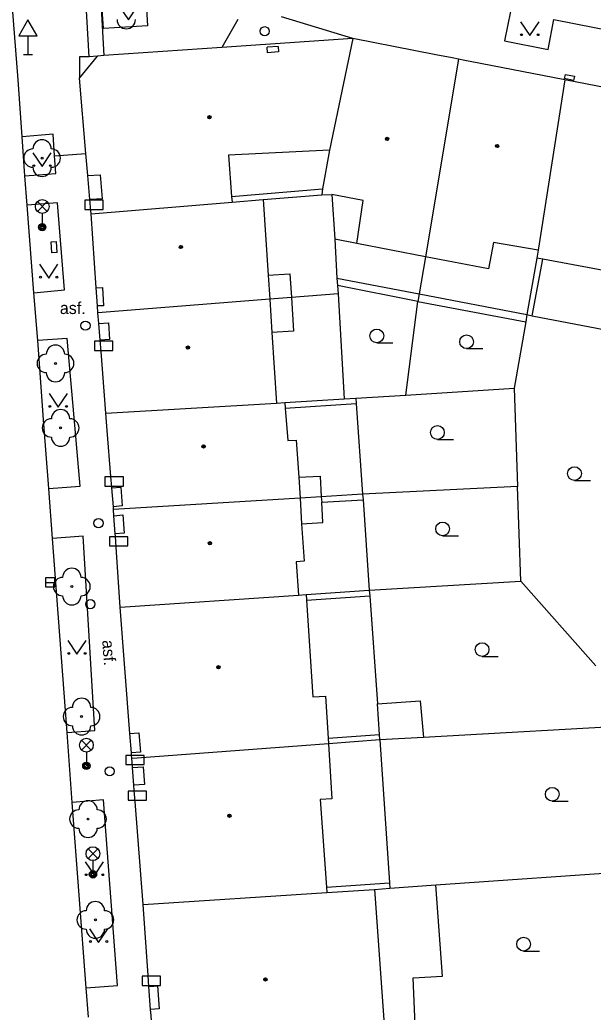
# Model space of a CAD drawing. Extents: x -596229 to -595156, y -1161237 to -1159376.
# Drawn here: x -596087.1 to -596055.9, y -1160946.5 to -1160892.5 of the extents above; entities that cross this region are included whole.
import ezdxf

# ---------------------------------------------------------------- set-up
doc = ezdxf.new("R2010")
doc.units = 0
for name, color, linetype in [('DOP - kresba z DSPS bez souradnic', 7, 'Continuous'), ('DOP - rozhrani ploch obecne', 7, 'Continuous'), ('Level 22', 7, 'Continuous'), ('Level 24', 7, 'Continuous'), ('Level 26', 7, 'Continuous'), ('Level 27', 7, 'Continuous'), ('Level 28', 7, 'Continuous'), ('Level 33', 7, 'Continuous'), ('Level 34', 7, 'Continuous'), ('Level 36', 7, 'Continuous'), ('Level 39', 7, 'Continuous'), ('plynovod - povrch.  znaky - PRIS skut. velikost', 7, 'Continuous'), ('slaboproud - povrch.  znaky a tel. budka skut. velikost', 7, 'Continuous'), ('Specificka linie pasportu komunikaci', 7, 'Continuous'), ('TM - budovy zdene_ betonove - NP', 7, 'Continuous'), ('TM - budovy zdene_ betonove - VN', 7, 'Continuous'), ('TM - budovy zdene_ betonove - VP', 7, 'Continuous'), ('TM - chodniky - VP', 7, 'Continuous'), ('TM - komunikace - VP', 7, 'Continuous'), ('TM - letecke snimky - pomocna linie', 7, 'Continuous'), ('TM - popis povrchu', 7, 'Continuous'), ('TM - rozhrani mezi zpev. plochami mezi sebou - VP', 7, 'Continuous'), ('TM - vstup do budovy - zdene_ betonove', 7, 'Continuous')]:
    doc.layers.add(name, color=color, linetype=linetype)

msp = doc.modelspace()

# ---------------------------------------------------------------- linework, layer by layer
at = {"layer": 'DOP - kresba z DSPS bez souradnic'}
for points in [[(-596075.59, -1160902.13), (-596070.64, -1160901.72)], [(-596068.78, -1160904.69), (-596069.98, -1160904.45)], [(-596059.23, -1160908.62), (-596058.65, -1160905.54)], [(-596073.61, -1160906.41), (-596072.42, -1160906.34)], [(-596072.42, -1160906.34), (-596072.34, -1160907.63)], [(-596069.86, -1160906.57), (-596065.38, -1160907.43)], [(-596072.34, -1160907.63), (-596072.22, -1160909.46)], [(-596065.38, -1160907.43), (-596059.52, -1160908.56)], [(-596072.22, -1160909.46), (-596073.4, -1160909.54)], [(-596072.67, -1160913.65), (-596068.81, -1160913.41)], [(-596071.94, -1160917.42), (-596070.78, -1160917.35)], [(-596070.78, -1160917.35), (-596070.71, -1160918.48)], [(-596070.71, -1160918.48), (-596070.69, -1160918.78)], [(-596070.69, -1160918.78), (-596068.44, -1160918.64)], [(-596070.62, -1160919.88), (-596070.69, -1160918.78)], [(-596071.78, -1160919.95), (-596070.62, -1160919.88)], [(-596071.51, -1160924.11), (-596068.07, -1160923.87)], [(-596067.54, -1160931.43), (-596067.66, -1160929.76)], [(-596070.34, -1160931.63), (-596067.54, -1160931.43)], [(-596067.52, -1160931.72), (-596067.54, -1160931.43)], [(-596070.43, -1160939.73), (-596067, -1160939.5)]]:
    msp.add_lwpolyline(points, dxfattribs=at)
at = {"layer": 'DOP - rozhrani ploch obecne'}
for points in [[(-596073.88, -1160902.29), (-596070.69, -1160902.03)], [(-596070.13, -1160902.02), (-596069.98, -1160904.45)], [(-596069.98, -1160904.45), (-596069.86, -1160906.57)], [(-596065.03, -1160905.41), (-596065.38, -1160907.43)], [(-596058.98, -1160905.48), (-596059.52, -1160908.56)], [(-596069.86, -1160906.57), (-596069.83, -1160906.98)], [(-596069.83, -1160906.98), (-596069.8, -1160907.43)], [(-596065.45, -1160907.85), (-596069.83, -1160906.98)], [(-596072.34, -1160907.63), (-596073.52, -1160907.72)], [(-596069.8, -1160907.43), (-596072.34, -1160907.63)], [(-596069.8, -1160907.43), (-596069.46, -1160913.15)], [(-596066.1, -1160912.94), (-596065.45, -1160907.85)], [(-596065.38, -1160907.43), (-596065.45, -1160907.85)], [(-596065.45, -1160907.85), (-596059.58, -1160908.95)], [(-596059.58, -1160908.95), (-596060.21, -1160912.57)], [(-596059.52, -1160908.56), (-596059.58, -1160908.95)], [(-596059.52, -1160908.56), (-596059.23, -1160908.62)], [(-596059.23, -1160908.62), (-596052.19, -1160909.97)], [(-596066.1, -1160912.94), (-596060.21, -1160912.57)], [(-596060.21, -1160912.57), (-596060.03, -1160917.92)], [(-596072.69, -1160913.35), (-596069.46, -1160913.15)], [(-596069.46, -1160913.15), (-596068.83, -1160913.11)], [(-596068.83, -1160913.11), (-596066.1, -1160912.94)], [(-596068.83, -1160913.11), (-596068.81, -1160913.41)], [(-596068.81, -1160913.41), (-596068.46, -1160918.34)], [(-596060.03, -1160917.92), (-596068.46, -1160918.34)], [(-596059.85, -1160923.07), (-596060.03, -1160917.92)], [(-596070.71, -1160918.48), (-596071.87, -1160918.55)], [(-596068.46, -1160918.34), (-596070.71, -1160918.48)], [(-596068.46, -1160918.34), (-596068.44, -1160918.64)], [(-596068.44, -1160918.64), (-596068.1, -1160923.57)], [(-596071.53, -1160923.81), (-596068.1, -1160923.57)], [(-596068.1, -1160923.57), (-596059.85, -1160923.07)], [(-596068.1, -1160923.57), (-596068.07, -1160923.87)], [(-596055.77, -1160927.69), (-596059.85, -1160923.07)], [(-596068.07, -1160923.87), (-596067.66, -1160929.76)], [(-596067.66, -1160929.76), (-596065.32, -1160929.6)], [(-596065.32, -1160929.6), (-596065.15, -1160931.59)], [(-596052.93, -1160930.9), (-596065.15, -1160931.59)], [(-596065.15, -1160931.59), (-596067.52, -1160931.72)], [(-596067.52, -1160931.72), (-596070.32, -1160931.93)], [(-596067.52, -1160931.72), (-596067, -1160939.5)], [(-596064.48, -1160939.62), (-596053.5, -1160938.85)], [(-596067.81, -1160939.86), (-596066.98, -1160939.8)], [(-596067, -1160939.5), (-596066.98, -1160939.8)], [(-596066.98, -1160939.8), (-596064.48, -1160939.62)]]:
    msp.add_lwpolyline(points, dxfattribs=at)
at = {"layer": 'Level 22'}
for centre in [(-596085.91, -1160900.04), (-596085.18, -1160911.22), (-596084.9, -1160914.73), (-596084.29, -1160923.37), (-596083.76, -1160930.45), (-596083.41, -1160936.03), (-596083.01, -1160941.52)]:
    msp.add_circle(centre, 0.05, dxfattribs=at)
for centre, start, end in [((-596081.33, -1160892.5), 180, 0), ((-596085.91, -1160899.54), 0, 180), ((-596086.41, -1160900.04), 90, 270), ((-596085.41, -1160900.04), 270, 90), ((-596085.91, -1160900.54), 180, 0), ((-596085.18, -1160910.72), 0, 180), ((-596085.68, -1160911.22), 90, 270), ((-596084.68, -1160911.22), 270, 90), ((-596085.18, -1160911.72), 180, 0), ((-596084.9, -1160914.23), 0, 180), ((-596085.4, -1160914.73), 90, 270), ((-596084.4, -1160914.73), 270, 90), ((-596084.9, -1160915.23), 180, 0), ((-596084.29, -1160922.87), 0, 180), ((-596084.79, -1160923.37), 90, 270), ((-596083.79, -1160923.37), 270, 90), ((-596084.29, -1160923.87), 180, 0), ((-596083.76, -1160929.95), 0, 180), ((-596084.26, -1160930.45), 90, 270), ((-596083.26, -1160930.45), 270, 90), ((-596083.76, -1160930.95), 180, 0), ((-596083.41, -1160935.53), 0, 180), ((-596083.91, -1160936.03), 90, 270), ((-596082.91, -1160936.03), 270, 90), ((-596083.41, -1160936.53), 180, 0), ((-596083.01, -1160941.02), 0, 180), ((-596083.51, -1160941.52), 90, 270), ((-596082.51, -1160941.52), 270, 90), ((-596083.01, -1160942.02), 180, 0)]:
    msp.add_arc(centre, 0.5, start, end, dxfattribs=at)
at = {"layer": 'Level 24'}
for points in [[(-596083.587, -1160902.838), (-596082.587, -1160902.838), (-596082.587, -1160902.338), (-596083.587, -1160902.338)], [(-596083.057, -1160910.508), (-596082.057, -1160910.508), (-596082.057, -1160910.008), (-596083.057, -1160910.008)], [(-596082.487, -1160917.898), (-596081.487, -1160917.898), (-596081.487, -1160917.398), (-596082.487, -1160917.398)], [(-596082.237, -1160921.158), (-596081.237, -1160921.158), (-596081.237, -1160920.658), (-596082.237, -1160920.658)], [(-596081.357, -1160933.068), (-596080.357, -1160933.068), (-596080.357, -1160932.568), (-596081.357, -1160932.568)], [(-596081.218, -1160935.009), (-596080.218, -1160935.009), (-596080.218, -1160934.509), (-596081.218, -1160934.509)], [(-596080.467, -1160945.088), (-596079.467, -1160945.088), (-596079.467, -1160944.588), (-596080.467, -1160944.588)]]:
    msp.add_lwpolyline(points, close=True, dxfattribs=at)
at = {"layer": 'Level 26'}
msp.add_circle((-596083.28, -1160924.33), 0.25, dxfattribs=at)
at = {"layer": 'Level 27'}
msp.add_line((-596085.72, -1160923.14), (-596085.22, -1160923.14), dxfattribs=at)
msp.add_lwpolyline([(-596085.72, -1160923.39), (-596085.22, -1160923.39), (-596085.22, -1160922.89), (-596085.72, -1160922.89)], close=True, dxfattribs=at)
at = {"layer": 'Level 28'}
for centre in [(-596073.79, -1160893.13), (-596083.55, -1160909.16), (-596082.84, -1160919.92), (-596082.23, -1160933.43)]:
    msp.add_circle(centre, 0.25, dxfattribs=at)
at = {"layer": 'Level 33'}
for p, q in [((-596086.165, -1160902.94), (-596085.635, -1160902.41)), ((-596086.165, -1160902.41), (-596085.635, -1160902.94)), ((-596085.9, -1160903.05), (-596085.9, -1160903.8)), ((-596083.765, -1160932.27), (-596083.235, -1160931.74)), ((-596083.765, -1160931.74), (-596083.235, -1160932.27)), ((-596083.5, -1160932.38), (-596083.5, -1160933.13)), ((-596083.405, -1160938.18), (-596082.875, -1160937.65)), ((-596083.405, -1160937.65), (-596082.875, -1160938.18)), ((-596083.14, -1160938.29), (-596083.14, -1160939.04))]:
    msp.add_line(p, q, dxfattribs=at)
for centre, radius in [((-596085.9, -1160902.675), 0.375), ((-596085.9, -1160903.8), 0.2), ((-596085.9, -1160903.8), 0.145), ((-596085.9, -1160903.8), 0.0876), ((-596083.5, -1160932.005), 0.375), ((-596083.5, -1160933.13), 0.2), ((-596083.5, -1160933.13), 0.145), ((-596083.5, -1160933.13), 0.0876), ((-596083.14, -1160937.915), 0.375), ((-596083.14, -1160939.04), 0.2), ((-596083.14, -1160939.04), 0.145), ((-596083.14, -1160939.04), 0.0876)]:
    msp.add_circle(centre, radius, dxfattribs=at)
at = {"layer": 'Level 34'}
for p, q in [((-596086.68, -1160893.382), (-596086.68, -1160894.4)), ((-596086.93, -1160894.4), (-596086.43, -1160894.4))]:
    msp.add_line(p, q, dxfattribs=at)
msp.add_lwpolyline([(-596087.18, -1160893.382), (-596086.18, -1160893.382), (-596086.68, -1160892.516)], close=True, dxfattribs=at)
at = {"layer": 'Level 36'}
for p, q in [((-596067.69, -1160910.095), (-596066.815, -1160910.095)), ((-596062.8, -1160910.415), (-596061.925, -1160910.415)), ((-596064.39, -1160915.355), (-596063.515, -1160915.355)), ((-596056.93, -1160917.595), (-596056.055, -1160917.595)), ((-596064.11, -1160920.605), (-596063.235, -1160920.605)), ((-596061.96, -1160927.175), (-596061.085, -1160927.175)), ((-596058.14, -1160935.055), (-596057.265, -1160935.055)), ((-596059.7, -1160943.215), (-596058.825, -1160943.215))]:
    msp.add_line(p, q, dxfattribs=at)
for points in [[(-596081.71, -1160891.76), (-596081.21, -1160892.51), (-596080.71, -1160891.76)], [(-596059.86, -1160892.62), (-596059.36, -1160893.37), (-596058.86, -1160892.62)], [(-596086.41, -1160899.75), (-596085.91, -1160900.5), (-596085.41, -1160899.75)], [(-596086.05, -1160905.82), (-596085.55, -1160906.57), (-596085.05, -1160905.82)], [(-596085.53, -1160912.86), (-596085.03, -1160913.61), (-596084.53, -1160912.86)], [(-596084.51, -1160926.31), (-596084.01, -1160927.06), (-596083.51, -1160926.31)], [(-596083.56, -1160938.36), (-596083.06, -1160939.11), (-596082.56, -1160938.36)], [(-596083.33, -1160942), (-596082.83, -1160942.75), (-596082.33, -1160942)]]:
    msp.add_lwpolyline(points, dxfattribs=at)
for centre, radius in [((-596059.81, -1160893.32), 0.05), ((-596058.911, -1160893.32), 0.05), ((-596086.36, -1160900.45), 0.05), ((-596085.461, -1160900.45), 0.05), ((-596086, -1160906.52), 0.05), ((-596085.101, -1160906.52), 0.05), ((-596067.69, -1160909.72), 0.375), ((-596062.8, -1160910.04), 0.375), ((-596085.48, -1160913.56), 0.05), ((-596084.581, -1160913.56), 0.05), ((-596064.39, -1160914.98), 0.375), ((-596056.93, -1160917.22), 0.375), ((-596064.11, -1160920.23), 0.375), ((-596061.96, -1160926.8), 0.375), ((-596084.46, -1160927.01), 0.05), ((-596083.561, -1160927.01), 0.05), ((-596058.14, -1160934.68), 0.375), ((-596083.51, -1160939.06), 0.05), ((-596082.611, -1160939.06), 0.05), ((-596059.7, -1160942.84), 0.375), ((-596083.28, -1160942.7), 0.05), ((-596082.381, -1160942.7), 0.05)]:
    msp.add_circle(centre, radius, dxfattribs=at)
at = {"layer": 'Level 39'}
for centre, radius in [((-596076.8, -1160897.81), 0.09), ((-596076.8, -1160897.81), 0.0398), ((-596067.13, -1160898.99), 0.09), ((-596067.13, -1160898.99), 0.0398), ((-596061.14, -1160899.38), 0.09), ((-596061.14, -1160899.38), 0.0398), ((-596078.35, -1160904.88), 0.09), ((-596078.35, -1160904.88), 0.0398), ((-596077.97, -1160910.36), 0.09), ((-596077.97, -1160910.36), 0.0398), ((-596077.12, -1160915.74), 0.09), ((-596077.12, -1160915.74), 0.0398), ((-596076.77, -1160921.01), 0.09), ((-596076.77, -1160921.01), 0.0398), ((-596076.31, -1160927.76), 0.09), ((-596076.31, -1160927.76), 0.0398), ((-596075.71, -1160935.85), 0.09), ((-596075.71, -1160935.85), 0.0398), ((-596073.75, -1160944.76), 0.09), ((-596073.75, -1160944.76), 0.0398)]:
    msp.add_circle(centre, radius, dxfattribs=at)
at = {"layer": 'plynovod - povrch.  znaky - PRIS skut. velikost'}
for points in [[(-596073.06, -1160893.96), (-596073.66, -1160894)], [(-596073.06, -1160893.96), (-596073.04, -1160894.26), (-596073.64, -1160894.3), (-596073.66, -1160894)]]:
    msp.add_lwpolyline(points, dxfattribs=at)
at = {"layer": 'slaboproud - povrch.  znaky a tel. budka skut. velikost'}
for points in [[(-596057.41, -1160895.48), (-596056.93, -1160895.58), (-596056.98, -1160895.82), (-596057.47, -1160895.71), (-596057.41, -1160895.48)], [(-596085.08, -1160905.18), (-596085.38, -1160905.2), (-596085.42, -1160904.6), (-596085.12, -1160904.58)], [(-596085.08, -1160905.18), (-596085.12, -1160904.58)]]:
    msp.add_lwpolyline(points, dxfattribs=at)
at = {"layer": 'Specificka linie pasportu komunikaci'}
for points in [[(-596075.26, -1160892.49), (-596076.12, -1160894.01)], [(-596069, -1160893.53), (-596072.87, -1160892.34)]]:
    msp.add_lwpolyline(points, dxfattribs=at)
at = {"layer": 'TM - budovy zdene_ betonove - NP'}
for points in [[(-596083.42, -1160900.99), (-596082.75, -1160900.95), (-596082.64, -1160902.26), (-596082.94, -1160902.27), (-596083.31, -1160902.29)], [(-596082.96, -1160907.1), (-596082.63, -1160907.08), (-596082.57, -1160908.08), (-596082.89, -1160908.09)], [(-596082.82, -1160909.04), (-596082.3, -1160909), (-596082.24, -1160909.91), (-596082.75, -1160909.95)], [(-596082.12, -1160918), (-596081.63, -1160917.96), (-596081.55, -1160918.98)], [(-596081.55, -1160918.98), (-596082.03, -1160919.02)], [(-596082, -1160919.51), (-596081.51, -1160919.47), (-596081.44, -1160920.46), (-596081.93, -1160920.5)], [(-596081.13, -1160931.37), (-596080.64, -1160931.33), (-596080.56, -1160932.38), (-596081.05, -1160932.42)], [(-596080.98, -1160933.22), (-596080.4, -1160933.18), (-596080.33, -1160934.15), (-596080.91, -1160934.19)], [(-596080.09, -1160945.15), (-596079.83, -1160945.13), (-596079.63, -1160945.11), (-596079.53, -1160946.36), (-596080, -1160946.4)]]:
    msp.add_lwpolyline(points, dxfattribs=at)
at = {"layer": 'TM - budovy zdene_ betonove - VN'}
for points in [[(-596083.35, -1160894.53), (-596083.87, -1160894.53), (-596083.88, -1160895.68)], [(-596082.89, -1160894.49), (-596083.35, -1160894.53)]]:
    msp.add_lwpolyline(points, dxfattribs=at)
at = {"layer": 'TM - budovy zdene_ betonove - VP'}
for points in [[(-596069, -1160893.53), (-596076.12, -1160894.01)], [(-596069, -1160893.53), (-596070.26, -1160899.6)], [(-596064.47, -1160894.41), (-596069, -1160893.53)], [(-596076.12, -1160894.01), (-596082.55, -1160894.45)], [(-596083.88, -1160895.68), (-596082.89, -1160894.49)], [(-596082.55, -1160894.45), (-596082.89, -1160894.49)], [(-596063.24, -1160894.65), (-596065.03, -1160905.41)], [(-596063.24, -1160894.65), (-596063.58, -1160894.58)], [(-596062.89, -1160894.72), (-596063.24, -1160894.65)], [(-596057.46, -1160895.78), (-596062.04, -1160894.88)], [(-596083.53, -1160899.79), (-596083.88, -1160895.68)], [(-596057.46, -1160895.78), (-596058.91, -1160905.06)], [(-596051.55, -1160896.92), (-596057.46, -1160895.78)], [(-596083.42, -1160900.99), (-596083.53, -1160899.79)], [(-596070.26, -1160899.6), (-596075.77, -1160899.88)], [(-596070.26, -1160899.6), (-596070.64, -1160901.72)], [(-596075.77, -1160899.88), (-596075.59, -1160902.13)], [(-596083.31, -1160902.29), (-596083.42, -1160900.99)], [(-596070.64, -1160901.72), (-596070.69, -1160902.03)], [(-596083.24, -1160903.07), (-596083.25, -1160902.91), (-596083.31, -1160902.29)], [(-596083.24, -1160903.07), (-596075.56, -1160902.43)], [(-596075.59, -1160902.13), (-596075.56, -1160902.43)], [(-596075.56, -1160902.43), (-596073.88, -1160902.29)], [(-596073.88, -1160902.29), (-596073.61, -1160906.41)], [(-596070.69, -1160902.03), (-596070.13, -1160902.02)], [(-596068.43, -1160902.34), (-596070.13, -1160902.02)], [(-596068.78, -1160904.69), (-596068.43, -1160902.34)], [(-596082.96, -1160907.1), (-596083.24, -1160903.07)], [(-596061.33, -1160904.64), (-596061.61, -1160906.07)], [(-596058.91, -1160905.06), (-596061.33, -1160904.64)], [(-596065.03, -1160905.41), (-596068.78, -1160904.69)], [(-596058.91, -1160905.06), (-596058.98, -1160905.48)], [(-596061.61, -1160906.07), (-596065.03, -1160905.41)], [(-596058.65, -1160905.54), (-596058.98, -1160905.48)], [(-596051.56, -1160906.86), (-596058.65, -1160905.54)], [(-596073.61, -1160906.41), (-596073.52, -1160907.72)], [(-596082.89, -1160908.09), (-596082.96, -1160907.1)], [(-596073.52, -1160907.72), (-596082.87, -1160908.46)], [(-596073.52, -1160907.72), (-596073.4, -1160909.54)], [(-596082.87, -1160908.46), (-596082.89, -1160908.09)], [(-596082.82, -1160909.04), (-596082.87, -1160908.46)], [(-596082.75, -1160909.95), (-596082.82, -1160909.04)], [(-596073.4, -1160909.54), (-596073.15, -1160913.38)], [(-596082.44, -1160913.92), (-596082.7, -1160910.57), (-596082.75, -1160909.95)], [(-596082.44, -1160913.92), (-596073.15, -1160913.38)], [(-596073.15, -1160913.38), (-596072.69, -1160913.35)], [(-596072.69, -1160913.35), (-596072.67, -1160913.65)], [(-596072.67, -1160913.65), (-596072.54, -1160915.42)], [(-596082.12, -1160918), (-596082.12, -1160917.95), (-596082.17, -1160917.37), (-596082.37, -1160914.88), (-596082.44, -1160913.92)], [(-596072.54, -1160915.42), (-596072.07, -1160915.39)], [(-596072.07, -1160915.39), (-596071.94, -1160917.42)], [(-596071.94, -1160917.42), (-596071.87, -1160918.55)], [(-596082.03, -1160919.02), (-596082.12, -1160918)], [(-596071.87, -1160918.55), (-596082.02, -1160919.18)], [(-596071.87, -1160918.55), (-596071.78, -1160919.95)], [(-596082.02, -1160919.18), (-596082.03, -1160919.02)], [(-596082, -1160919.51), (-596082.02, -1160919.18)], [(-596081.93, -1160920.5), (-596082, -1160919.51)], [(-596071.78, -1160919.95), (-596071.65, -1160921.99)], [(-596081.66, -1160924.5), (-596081.88, -1160921.22), (-596081.92, -1160920.62), (-596081.93, -1160920.5)], [(-596071.65, -1160921.99), (-596072.08, -1160922.02)], [(-596072.08, -1160922.02), (-596071.96, -1160923.84)], [(-596081.66, -1160924.5), (-596071.96, -1160923.84)], [(-596071.96, -1160923.84), (-596071.53, -1160923.81)], [(-596071.53, -1160923.81), (-596071.51, -1160924.11)], [(-596071.51, -1160924.11), (-596071.18, -1160929.38)], [(-596081.13, -1160931.37), (-596081.66, -1160924.5)], [(-596071.18, -1160929.38), (-596070.48, -1160929.33)], [(-596070.48, -1160929.33), (-596070.34, -1160931.63)], [(-596081.05, -1160932.42), (-596081.13, -1160931.37)], [(-596070.34, -1160931.63), (-596070.32, -1160931.93)], [(-596070.32, -1160931.93), (-596080.73, -1160932.71)], [(-596070.32, -1160931.93), (-596070.13, -1160934.92)], [(-596081.02, -1160932.73), (-596081.04, -1160932.53), (-596081.05, -1160932.42)], [(-596080.73, -1160932.71), (-596081.02, -1160932.73)], [(-596080.98, -1160933.22), (-596080.99, -1160933.13), (-596081.02, -1160932.73)], [(-596080.91, -1160934.19), (-596080.98, -1160933.22)], [(-596080.41, -1160940.68), (-596080.84, -1160935.07), (-596080.89, -1160934.47), (-596080.91, -1160934.19)], [(-596070.13, -1160934.92), (-596070.78, -1160934.97)], [(-596070.78, -1160934.97), (-596070.43, -1160939.73)], [(-596070.43, -1160939.73), (-596070.41, -1160940.03)], [(-596080.41, -1160940.68), (-596070.41, -1160940.03)], [(-596070.41, -1160940.03), (-596067.81, -1160939.86)], [(-596067.81, -1160939.86), (-596067.12, -1160949.51)], [(-596080.09, -1160945.15), (-596080.13, -1160944.55), (-596080.41, -1160940.68)], [(-596080, -1160946.4), (-596080.09, -1160945.15)], [(-596079.69, -1160950.68), (-596079.94, -1160947.32), (-596079.98, -1160946.72), (-596080, -1160946.4)]]:
    msp.add_lwpolyline(points, dxfattribs=at)
at = {"layer": 'TM - chodniky - VP'}
for points in [[(-596080.27, -1160891.25), (-596080.17, -1160892.83), (-596082.56, -1160892.99), (-596082.67, -1160891.41), (-596080.27, -1160891.25)], [(-596060.42, -1160892.05), (-596060.73, -1160893.66), (-596058.37, -1160894.12), (-596058.06, -1160892.5)], [(-596085.24, -1160899.92), (-596085.3, -1160898.74), (-596087, -1160898.88)], [(-596086.84, -1160901.01), (-596085.16, -1160900.88), (-596085.24, -1160899.92)], [(-596086.36, -1160907.38), (-596084.69, -1160907.21), (-596085.07, -1160902.48), (-596086.72, -1160902.6)], [(-596085.54, -1160918.03), (-596083.84, -1160917.9), (-596084.17, -1160914.159), (-596084.55, -1160909.86), (-596086.15, -1160909.97)], [(-596084.55, -1160931.32), (-596083.04, -1160931.21), (-596083.68, -1160920.63), (-596085.34, -1160920.75)], [(-596083.51, -1160945.22), (-596081.8, -1160945.09), (-596082.57, -1160934.99), (-596084.27, -1160935.12)]]:
    msp.add_lwpolyline(points, dxfattribs=at)
at = {"layer": 'TM - komunikace - VP'}
for points in [[(-596087, -1160898.88), (-596087.22, -1160895.78), (-596087.59, -1160890.92)], [(-596058.06, -1160892.5), (-596053.53, -1160893.38)], [(-596086.84, -1160901.01), (-596087, -1160898.88)], [(-596086.72, -1160902.6), (-596086.84, -1160901.01)], [(-596086.36, -1160907.38), (-596086.72, -1160902.6)], [(-596086.15, -1160909.97), (-596086.36, -1160907.38)], [(-596085.54, -1160918.03), (-596085.81, -1160914.53), (-596086.15, -1160909.97)], [(-596085.34, -1160920.75), (-596085.54, -1160918.03)], [(-596084.55, -1160931.32), (-596085.34, -1160920.75)], [(-596084.27, -1160935.12), (-596084.55, -1160931.32)], [(-596083.51, -1160945.22), (-596084.27, -1160935.12)], [(-596083.39, -1160946.82), (-596083.51, -1160945.22)]]:
    msp.add_lwpolyline(points, dxfattribs=at)
at = {"layer": 'TM - letecke snimky - pomocna linie'}
msp.add_lwpolyline([(-596065.51, -1160949.38), (-596065.71, -1160944.67), (-596064.12, -1160944.59), (-596064.48, -1160939.62)], dxfattribs=at)
at = {"layer": 'TM - rozhrani mezi zpev. plochami mezi sebou - VP'}
for points in [[(-596083.35, -1160894.53), (-596083.7, -1160888.54), (-596085.45, -1160887.98), (-596084.81, -1160887.35), (-596082.92, -1160887.94), (-596082.55, -1160894.45)], [(-596085.24, -1160899.92), (-596083.53, -1160899.79)]]:
    msp.add_lwpolyline(points, dxfattribs=at)
at = {"layer": 'TM - vstup do budovy - zdene_ betonove'}
for points in [[(-596063.58, -1160894.58), (-596064.47, -1160894.41)], [(-596062.04, -1160894.88), (-596062.89, -1160894.72)]]:
    msp.add_lwpolyline(points, dxfattribs=at)

# ---------------------------------------------------------------- texts
at = {"layer": 'TM - popis povrchu'}
msp.add_text('asf.', height=0.65, dxfattribs=at).set_placement((-596084.94, -1160908.53))
msp.add_text('asf.', height=0.65, rotation=274.25, dxfattribs=at).set_placement((-596082.64, -1160926.3))

doc.saveas('drawing.dxf')
